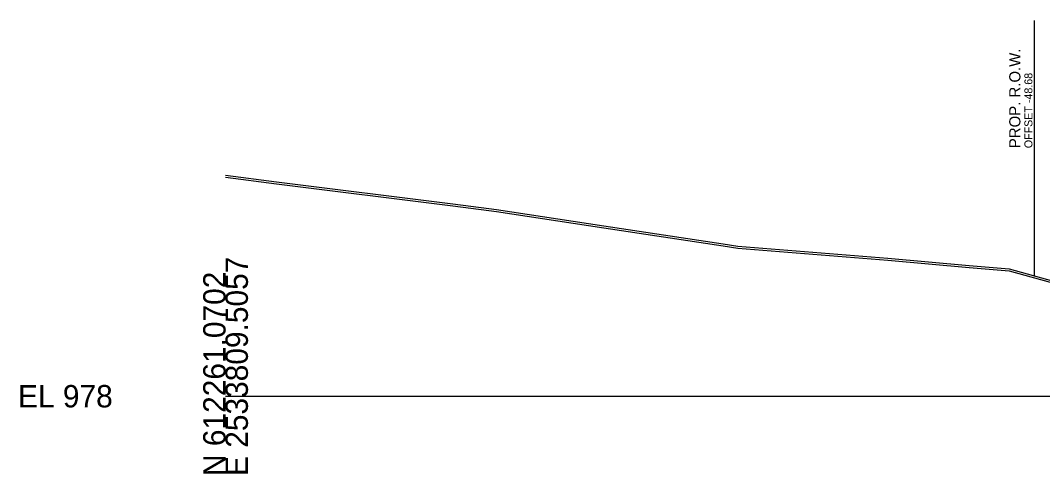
# Model space of a CAD drawing. Extents: x -120 to 2876, y -25 to 8560.
# Drawn here: x -25.7 to 102.3, y 5990.3 to 6047.1 of the extents above; entities that cross this region are included whole.
import ezdxf

# ---------------------------------------------------------------- set-up
doc = ezdxf.new("R2010")
doc.units = 0
for name, color, linetype in [('DESIGN - ROW - Right-of-Way and Easement Labels', 7, 'Continuous'), ('DESIGN - ROW - Right-of-Way Linework', 7, 'Continuous'), ('DESIGN - SHEET - Light Grid', 7, 'Continuous'), ('SURVEY - GROUND - Bottom of Topsoil Layer', 7, 'Continuous'), ('SURVEY - GROUND - Top of Ground', 7, 'Continuous')]:
    doc.layers.add(name, color=color, linetype=linetype)

msp = doc.modelspace()

# ---------------------------------------------------------------- linework, layer by layer
at = {"layer": 'DESIGN - ROW - Right-of-Way Linework'}
msp.add_line((101.32, 6015.08), (101.32, 6047.08), dxfattribs=at)
at = {"layer": 'DESIGN - SHEET - Light Grid'}
msp.add_line((0, 6000), (150, 6000), dxfattribs=at)
at = {"layer": 'SURVEY - GROUND - Bottom of Topsoil Layer'}
for p, q in [((0, 6027.44), (6.38, 6026.6)), ((6.38, 6026.6), (28.47, 6023.87)), ((28.47, 6023.87), (32.98, 6023.25)), ((32.98, 6023.25), (33.94, 6023.15)), ((33.94, 6023.15), (47.37, 6021.09)), ((47.37, 6021.09), (62.33, 6018.83)), ((62.33, 6018.83), (64.16, 6018.56)), ((64.16, 6018.56), (82.95, 6017.05)), ((82.95, 6017.05), (93.14, 6016.11)), ((93.14, 6016.11), (98.14, 6015.72)), ((98.14, 6015.72), (122.92, 6008.82))]:
    msp.add_line(p, q, dxfattribs=at)
at = {"layer": 'SURVEY - GROUND - Top of Ground'}
msp.add_lwpolyline([(0, 6027.69), (6.38, 6026.85), (28.47, 6024.12), (32.98, 6023.5), (33.94, 6023.4), (47.37, 6021.34), (62.33, 6019.08), (64.16, 6018.81), (82.95, 6017.3), (93.14, 6016.36), (98.14, 6015.97), (122.92, 6009.07)], dxfattribs=at)

# ---------------------------------------------------------------- texts
at = {"layer": 'DESIGN - ROW - Right-of-Way and Easement Labels'}
for s, height, p in [('PROP. R.O.W.', 1.4, (99.57, 6031.08)), ('OFFSET -48.68', 1, (101.07, 6031.08))]:
    msp.add_text(s, height=height, rotation=90, dxfattribs=at).set_placement(p)
at = {"layer": 'DESIGN - SHEET - Light Grid'}
for s, p in [('E 2533809.5057', (2.8, 5990)), ('N 612261.0702', (0, 5990))]:
    msp.add_text(s, height=2.8, rotation=90, dxfattribs=at).set_placement(p)
msp.add_text('EL 978', height=2.8, dxfattribs=at).set_placement((-26, 5998.6))

doc.saveas('drawing.dxf')
